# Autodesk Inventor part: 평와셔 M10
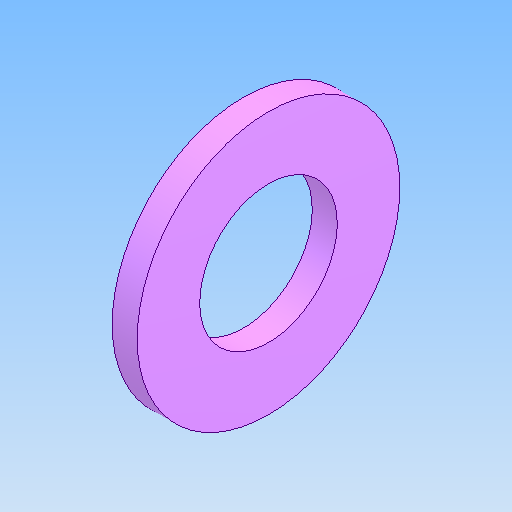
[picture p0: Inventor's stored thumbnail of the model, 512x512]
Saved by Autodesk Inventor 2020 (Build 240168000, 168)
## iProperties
Created: 2024-09
Part Number: 평와셔 M10
Material: 강철, 연강
Description: 평면 와셔
Document SubType Name: Modeling
Designer: oem
Density: 7.85 g/cm^3
Appearance: 기본값
Author: jhkim
Sending System: Autodesk Inventor 2025
Preprocessor: ST-DEVELOPER v20
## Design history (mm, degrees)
feature "Solid1"
node "솔리드1"
